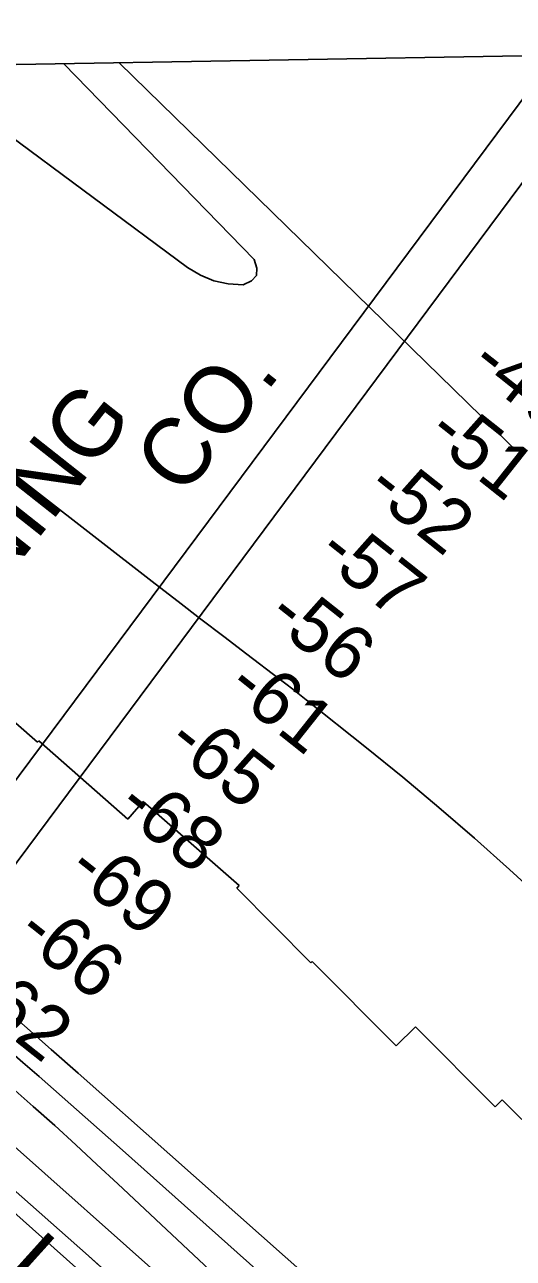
# Model space of a CAD drawing. Extents: x 3903937 to 3942190, y 260677 to 286651.
# Drawn here: x 3916965 to 3917570, y 282879 to 284405 of the extents above; entities that cross this region are included whole.
import ezdxf

# ---------------------------------------------------------------- set-up
doc = ezdxf.new("R2010")
doc.units = 0
for name, color, linetype in [('V-GRID-FRAM', 7, 'Continuous'), ('V-RIVR-EDGE', 7, 'Continuous'), ('V-RIVR-RANG', 7, 'Continuous'), ('V-RRAP-RVMT', 7, 'Continuous'), ('V-TOPO-DPTH', 7, 'Continuous'), ('V-TOPO-MAJR', 7, 'Continuous'), ('V-TOPO-MINR', 7, 'Continuous'), ('V-TOPO-WATR-IDEN', 7, 'Continuous'), ('V-UTIL-IDEN', 7, 'Continuous'), ('V-UTIL-LINE', 7, 'Continuous')]:
    doc.layers.add(name, color=color, linetype=linetype)

msp = doc.modelspace()

# ---------------------------------------------------------------- linework, layer by layer
at = {"layer": 'V-GRID-FRAM'}
msp.add_lwpolyline([(3907892.2, 284196.1), (3939773.2, 284757.2), (3940101.1, 266577.6), (3908204.3, 266016.2), (3907892.2, 284196.1)], dxfattribs=at)
at = {"layer": 'V-RIVR-EDGE'}
msp.add_spline([(3917425.1, 282263.8), (3917389, 282294.2), (3917376.9, 282301.5), (3917364.7, 282305.9), (3917358.9, 282312.7), (3917351.7, 282313.2), (3917339.5, 282313.8), (3917337.6, 282316.7), (3917335.7, 282327.9), (3917333.2, 282330.8), (3917324.5, 282334.2), (3917318.2, 282334.7), (3917313.8, 282338.1), (3917308, 282350.3), (3917295.5, 282366.8), (3917283.8, 282379), (3917272.2, 282386.3), (3917256.7, 282392.6), (3917245, 282398), (3917231.4, 282406.8), (3917219.3, 282412.6), (3917183.4, 282425.8), (3917138.3, 282440), (3917074.7, 282459.6), (3917032, 282479.1), (3916988.4, 282500.1), (3916967.5, 282515.7), (3916953.5, 282531.3), (3916939.4, 282546.9), (3916923.4, 282556.6), (3916909.4, 282558.6), (3916896.3, 282564), (3916886.6, 282574.7), (3916876.4, 282580.1), (3916858.4, 282585), (3916838.5, 282588.4), (3916812.3, 282597.2), (3916792, 282609.9), (3916782.3, 282615.7), (3916776, 282619.6), (3916763.8, 282627.4), (3916749.3, 282634.3), (3916741, 282637.7), (3916730.4, 282642.1), (3916723.6, 282648.4), (3916721.7, 282654.3), (3916721.7, 282661.1), (3916724.1, 282668.3), (3916732.9, 282687.7), (3916733.4, 282696), (3916730.5, 282710.6), (3916725.2, 282723.7), (3916724.8, 282730.5), (3916727.2, 282735.3), (3916735.5, 282744.1), (3916736.9, 282748.4), (3916736.5, 282752.3), (3916730.2, 282755.7), (3916729.2, 282758.2), (3916731.6, 282760.1), (3916731.6, 282763.5), (3916727.8, 282770.8), (3916727.3, 282772.7), (3916727.8, 282778.1), (3916727.8, 282783.9), (3916726.9, 282799), (3916725.5, 282818.4), (3916729.9, 282838.8), (3916731.4, 282846.1), (3916733.8, 282854.8), (3916737.7, 282862.1), (3916742.1, 282864.5), (3916751.8, 282863.5), (3916755.7, 282865.4), (3916757.2, 282868.8), (3916756.2, 282873.2), (3916756.2, 282883.9), (3916757.7, 282894.1), (3916764, 282902.3), (3916767, 282910.1), (3916770.4, 282913), (3916781, 282908.1), (3916789.3, 282907.6), (3916789.3, 282910), (3916782, 282918.8), (3916778.7, 282923.6), (3916763.6, 282935.3), (3916726.8, 282963.6), (3916714.2, 282972.9), (3916689, 282991.4), (3916632.3, 283034.2), (3916610, 283048.9), (3916578, 283066.9), (3916543, 283088.9), (3916510.1, 283112.7), (3916469.8, 283140.5), (3916444.2, 283160.5), (3916369, 283219), (3916281.3, 283284.2), (3916175.1, 283366.6), (3916089.8, 283429.9), (3915988, 283506.4), (3915917.7, 283560), (3915863.9, 283597.5), (3915811.6, 283639.9), (3915738.9, 283704.7)], degree=3, dxfattribs=at)
at = {"layer": 'V-RRAP-RVMT'}
for p, q in [((3916868, 283615.8), (3916980.7, 283517.4)), ((3916980.7, 283517.4), (3916982.1, 283519)), ((3916982.1, 283519), (3917092.5, 283422.4)), ((3917092.5, 283422.4), (3917111.3, 283444.1)), ((3917111.3, 283444.1), (3917230, 283340.3)), ((3917230, 283340.3), (3917227.2, 283337)), ((3917227.2, 283337), (3917319, 283244.7)), ((3917319, 283244.7), (3917320.6, 283246.3)), ((3917320.6, 283246.3), (3917424.5, 283141.9)), ((3917424.5, 283141.9), (3917448.4, 283165.5)), ((3917448.4, 283165.5), (3917546.9, 283066.4)), ((3917546.9, 283066.4), (3917555.9, 283075.3)), ((3917555.9, 283075.3), (3917654.9, 282976))]:
    msp.add_line(p, q, dxfattribs=at)
at = {"layer": 'V-TOPO-DPTH'}
for points in [[(3917139.6, 282850.9), (3916940.9, 283027.3), (3916915.1, 283049.9), (3916889, 283072.3), (3916862.7, 283094.3), (3916836.1, 283116), (3916519.5, 283371.3), (3916477.1, 283405.5), (3916434.6, 283439.7), (3916392.2, 283474), (3916349.8, 283508.2), (3916284.7, 283560.9), (3916274.9, 283568.9), (3916265.1, 283576.9), (3916255.4, 283585), (3916245.8, 283593.1), (3915749.5, 284013.5)], [(3917139.6, 282850.9), (3916940.9, 283027.3), (3916915.1, 283049.9), (3916889, 283072.3), (3916862.7, 283094.3), (3916836.1, 283116), (3916519.5, 283371.3), (3916477.1, 283405.5), (3916434.6, 283439.7), (3916392.2, 283474), (3916349.8, 283508.2), (3916284.7, 283560.9), (3916274.9, 283568.9), (3916265.1, 283576.9), (3916255.4, 283585), (3916245.8, 283593.1), (3915749.5, 284013.5)], [(3916938.2, 283099.9), (3916975.3, 283066.8), (3917001.8, 283043.2), (3917028, 283019.3), (3917054.1, 282995.3), (3917080.1, 282971.1), (3917421.3, 282651.3)], [(3917421.3, 282651.3), (3917080.1, 282971.1), (3917054.1, 282995.3), (3917028, 283019.3), (3917001.8, 283043.2), (3916975.3, 283066.8), (3916938.2, 283099.9)], [(3917057.6, 282869.5), (3917043.7, 282882), (3917007.8, 282913.9), (3916971.9, 282945.7), (3916935.9, 282977.4)], [(3916935.9, 282977.4), (3916971.9, 282945.7), (3917007.8, 282913.9), (3917043.7, 282882), (3917079.4, 282850)]]:
    msp.add_lwpolyline(points, dxfattribs=at)
at = {"layer": 'V-TOPO-MAJR'}
for points in [[(3917013.1, 284356.6), (3917248.8, 284114.3), (3917252.2, 284103.6), (3917251.6, 284094.6), (3917245.3, 284088.1), (3917235.1, 284083.3), (3917216.6, 284084.5), (3917198.8, 284088), (3917182.1, 284095), (3917166.1, 284104.5), (3916932.3, 284277.9), (3916907, 284296.8), (3916882, 284316), (3916857.2, 284335.5), (3916834.8, 284353.5)], [(3917569.7, 283881.1), (3917559.9, 283891), (3917550, 283900.9), (3917540.1, 283910.8), (3917530.1, 283920.5), (3917081.5, 284357.8)], [(3915822.6, 284039), (3915880.8, 283992), (3915939.2, 283945.3), (3915997.7, 283898.9), (3916056.5, 283852.8), (3916271.9, 283684.3), (3916297, 283664.7), (3916322.1, 283645), (3916347.2, 283625.3), (3916372.2, 283605.6), (3916432.4, 283558.3), (3916487.3, 283514.7), (3916542, 283470.8), (3916596.4, 283426.5), (3916650.5, 283381.9), (3916901.3, 283173.6), (3916921.8, 283156.4), (3916942.2, 283139), (3916962.5, 283121.5), (3916982.7, 283103.8), (3917085.6, 283012.8), (3917151, 282954.8), (3917216.3, 282896.6), (3917281.5, 282838.3)]]:
    msp.add_lwpolyline(points, dxfattribs=at)
at = {"layer": 'V-TOPO-MINR'}
for points in [[(3915807.6, 284118.3), (3915997.5, 283985.9), (3916061, 283940.6), (3916123.9, 283894.4), (3916185.8, 283846.9), (3916247, 283798.5), (3916340.5, 283722.9), (3916354.4, 283711.5), (3916368.1, 283700), (3916381.6, 283688.2), (3916395, 283676.4), (3916708.2, 283393.8), (3916750.7, 283355.7), (3916793.2, 283317.6), (3916835.9, 283279.8), (3916878.7, 283242.1), (3916897.8, 283225.3), (3916931.1, 283196), (3916964.3, 283166.7), (3916997.6, 283137.3), (3917030.8, 283107.9), (3917371.1, 282806.3)], [(3917802.8, 283142.6), (3917564.6, 283359.9), (3917521.3, 283398.7), (3917477.4, 283436.8), (3917432.8, 283474.1), (3917387.6, 283510.7), (3917313.2, 283569.9), (3917304.8, 283576.5), (3917296.4, 283583), (3917288, 283589.5), (3917279.6, 283596), (3917239.6, 283626.3), (3917211.2, 283648), (3917182.8, 283669.7), (3917154.5, 283691.5), (3917126.2, 283713.3), (3916681.6, 284058.5)], [(3915749.5, 284013.5), (3916245.8, 283593.1), (3916255.4, 283585), (3916265.1, 283576.9), (3916274.9, 283568.9), (3916284.7, 283560.9), (3916349.8, 283508.2), (3916392.2, 283474), (3916434.6, 283439.7), (3916477.1, 283405.5), (3916519.5, 283371.3), (3916836.1, 283116), (3916862.7, 283094.3), (3916889, 283072.3), (3916915.1, 283049.9), (3916940.9, 283027.3), (3917139.6, 282850.9)], [(3916938.2, 283099.9), (3916975.3, 283066.8), (3917001.8, 283043.2), (3917028, 283019.3), (3917054.1, 282995.3), (3917080.1, 282971.1), (3917421.3, 282651.3)], [(3916904.9, 282977.1), (3917364.6, 282567.7)], [(3916935.9, 282977.4), (3916971.9, 282945.7), (3917007.8, 282913.9), (3917043.7, 282882), (3917079.4, 282850)]]:
    msp.add_lwpolyline(points, dxfattribs=at)
at = {"layer": 'V-UTIL-LINE'}
for p, q in [((3916606.8, 283005.3), (3917621.5, 284367.3)), ((3916653.2, 282964.1), (3917699.7, 284368.7))]:
    msp.add_line(p, q, dxfattribs=at)

# ---------------------------------------------------------------- texts
at = {"layer": 'V-RIVR-RANG'}
for s, p in [('-46', (3917512.8, 283979.8)), ('-51', (3917459.8, 283894.3)), ('-52', (3917384.4, 283826.4)), ('-57', (3917323.9, 283746.8)), ('-56', (3917261.8, 283668.4)), ('-61', (3917212, 283580.2)), ('-65', (3917137.4, 283511.7)), ('-68', (3917075.9, 283432.9)), ('-69', (3917014.2, 283354.2)), ('-66', (3916951.6, 283276.2)), ('-62', (3916887.2, 283199.7))]:
    msp.add_text(s, height=67, rotation=321.5637, dxfattribs=at).set_placement(p)
at = {"layer": 'V-TOPO-WATR-IDEN'}
msp.add_text('L.W.R.P.', height=83, rotation=317.9407, dxfattribs=at).set_placement((3916931.3, 282855.5))
at = {"layer": 'V-UTIL-IDEN'}
for s, p in [(' CO. ', (3917141.3, 283794.4)), ('GULF REFINING', (3916569.4, 283247))]:
    msp.add_text(s, height=83, rotation=51.7037, dxfattribs=at).set_placement(p)

doc.saveas('drawing.dxf')
